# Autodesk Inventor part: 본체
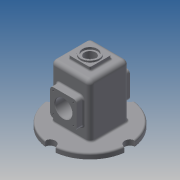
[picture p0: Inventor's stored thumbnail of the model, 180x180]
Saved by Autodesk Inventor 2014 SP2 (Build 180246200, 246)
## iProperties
Created: 2018-07
Part Number: 본체
Material: Generic
Document SubType Name: Modeling
Designer: cm
Density: 1 g/cm^3
Appearance: Default
Author: cm
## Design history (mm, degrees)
sketch "스케치1"
  geometry: L1 (-37, -37)-(37, -37); L2 (37, -37)-(37, 37); L3 (37, 37)-(-37, 37); L4 (-37, 37)-(-37, -37); L5 (-37, -37)-(37, 37); L6 (37, -37)-(-37, 37); 1 further point
  constraints: 12 end point, 2 midpoint, 2 parallel, 1 horizontal, 1 perpendicular
  dimensions: "d0" = 74 distance of L3.end L2.end; "d1" = 74 distance of L2.end L1.end
extrude "돌출1" new body sketch "스케치1" distance "d2" = 110; taper "d3" = 0 deg
feature "쉘1" dims "d5" = 5
sketch "스케치3"
  geometry: L1 (-37, -37)-(37, -37) reference; L2 (-37, 37)-(-37, -37) reference; L3 (37, 37)-(-37, 37) reference; L4 (37, -37)-(37, 37) reference; L5 (-29, -37)-(29, -37); L6 (37, -29)-(37, 29); L7 (29, 37)-(-29, 37); L8 (-37, 29)-(-37, -29); L9 (-37, -37)-(37, 37); L10 (37, -37)-(-37, 37); C1 r 75 at (0, 0); A1 r 8 centre (-29, -29) between (-37, -29) and (-29, -37) reference; A2 r 8 centre (-29, 29) between (-29, 37) and (-37, 29) reference; A3 r 8 centre (29, 29) between (37, 29) and (29, 37) reference; A4 r 8 centre (29, -29) between (29, -37) and (37, -29) reference; A5 r 8 centre (29, -29) between (29, -37) and (37, -29); A6 r 8 centre (-29, -29) between (-37, -29) and (-29, -37); A7 r 8 centre (-29, 29) between (-29, 37) and (-37, 29); A8 r 8 centre (29, 29) between (37, 29) and (29, 37); 1 further point
  constraints: 12 end point, 8 point on circle, 8 point on line, 8 tangent, 5 centre point, 3 equal radius, 2 midpoint, 2 parallel, 1 coincident, 1 horizontal, 1 perpendicular
  dimensions: "d9" = 150 diameter of C1; "d10" = 74 distance of L2.start L3.start; "d11" = 74 distance of L3.start L1.end; "d12" = 8 radius of A5
extrude "돌출3" join sketch "스케치3" distance "d13" = 10; taper "d14" = 0 deg
sketch "스케치4"
  geometry: L1 (0, 0)-(0, 55); L2 (-29, 105)-(29, 105) reference; L3 (-32, 0)-(-32, 102) reference; L4 (32, 102)-(32, 0) reference; L5 (0, 55)-(-49.301, 55); L6 (-32, 80)-(-25, 77.452); L7 (-25, 77.452)-(-25, 55); L8 (-32, 80)-(-32, 55); A1 r 3 centre (-29, 102) between (-29, 105) and (-32, 102) reference; A2 r 3 centre (29, 102) between (32, 102) and (29, 105) reference
  constraints: 10 end point, 4 point on line, 2 perpendicular, 1 vertical
  dimensions: "d15" = 55 distance of L1.start L1.end; "d16" = 7 distance between parallel lines of L7 L3; "d17" = 50 diameter of L6.start L5; "d18" = 110 deg angle of L6 L3
revolve "회전1" sketch "스케치4" stored, may be unused: angle "d19" = 90 deg
fillet "모깎기2" dims "d20" = 8
fillet "모깎기3" dims "d21" = 3
sketch "스케치6"
  geometry: L1 (0, 92)-(58, 92) reference; L2 (29, -10)-(29, 45); L3 (4, 70)-(54, 70); L4 (54, 70)-(54, 20); L5 (54, 20)-(4, 20); L6 (4, 20)-(4, 70); L7 (4, 70)-(54, 20); L8 (54, 70)-(4, 20)
  constraints: 14 end point, 2 midpoint, 2 parallel, 2 perpendicular, 1 horizontal
  dimensions: "d22" = 55 distance of L2.start L2.end; "d23" = 50 distance of L4.end L5.end; "d24" = 50 distance of L3.end L4.end
extrude "돌출4" join sketch "스케치6" distance "d25" = 13; taper "d26" = 0 deg
sketch "스케치7"
  geometry: L1 (54, 20)-(54, 70) reference; L2 (29, -10)-(29, 45); C1 r 16 at (29, 45)
  constraints: 2 end point, 1 centre point, 1 coincident, 1 parallel
  dimensions: "d27" = 55 distance of L2.start L2.end; "d28" = 32 diameter of C1
extrude "돌출5" cut sketch "스케치7" stored distance "d29" = 13; taper "d30" = 0 deg
sketch "스케치8"
  geometry: L1 (-20, 20)-(20, 20); L2 (20, 20)-(20, -20); L3 (20, -20)-(-20, -20); L4 (-20, -20)-(-20, 20); L5 (-20, 20)-(20, -20); L6 (20, 20)-(-20, -20); 1 further point
  constraints: 12 end point, 2 midpoint, 2 parallel, 1 horizontal, 1 perpendicular
  dimensions: "d31" = 40 distance of L2.end L3.end; "d32" = 40 distance of L1.end L2.end
extrude "돌출6" join sketch "스케치8" distance "d33" = 7; taper "d34" = 0 deg
sketch "스케치9"
  geometry: C1 r 17.5 at (0, 0); 1 further point
  constraints: 1 centre point, 1 coincident
  dimensions: "d35" = 35 diameter of C1
extrude "돌출7" join sketch "스케치9" distance "d36" = 3; taper "d37" = 0 deg
sketch "스케치10"
  geometry: C1 r 17.5 at (0, 0) reference; 1 further point
  constraints: 1 coincident
hole "구멍1" sketch "스케치10" at (0, 0) diameter "d38" = 21; stored, may be unused: countersink angle "d42" = 90 deg, drill point angle "d44" = 118 deg; dims "d39" = 6, "d40" = 28, "d41" = 4, "d43" = 8
fillet "모깎기4" dims "d45" = 6
fillet "모깎기5" dims "d46" = 3
fillet "모깎기6" dims "d47" = 6
fillet "모깎기7" dims "d48" = 3
sketch "스케치11"
  geometry: A1 r 6 centre (10, 26) between (4, 26) and (10, 20) reference; A2 r 6 centre (48, 26) between (48, 20) and (54, 26) reference; A3 r 6 centre (48, 64) between (54, 64) and (48, 70) reference; A4 r 6 centre (10, 64) between (10, 70) and (4, 64) reference; 5 further points
  constraints: 4 coincident
hole "구멍2" sketch "스케치11" at (10, 64), (48, 64), (48, 26), (10, 26) diameter "d49" = 3.242; stored, may be unused: countersink angle "d53" = 90 deg, drill point angle "d55" = 118 deg; dims "d50" = 8, "d51" = 28, "d52" = 4, "d54" = 10
fillet "모깎기8" dims "d56" = 3
fillet "모깎기9" dims "d57" = 3
fillet "모깎기10" dims "d58" = 3
fillet "모깎기11" dims "d59" = 3
sketch "스케치12"
  geometry: L1 (29, 40)-(-29, 40) reference; L2 (0, -75)-(0, 75); L3 (-75, 0)-(75, 0); C1 r 72 at (0, 0) reference; C2 r 10 at (0, 75); C3 r 10 at (75, 0); C4 r 10 at (0, -75); C5 r 10 at (-75, 0); A1 r 75 centre (0, 0) between (0, -75) and (0, 75) reference; 1 further point
  constraints: 5 coincident, 4 centre point, 4 end point, 4 point on circle, 2 midpoint, 2 perpendicular
  dimensions: "d61" = 20 diameter of C2; "d62" = 20 diameter of C3; "d63" = 20 diameter of C4; "d64" = 20 diameter of C5
extrude "돌출8" cut sketch "스케치12" stored distance "d65" = 3; taper "d66" = 0 deg
chamfer "모따기1" distance "d67" = 1; stored, may be unused: second distance "d68" = 2, angle "d69" = 45 deg
sketch "스케치14"
  geometry: L1 (11.5, -18)-(46.5, -18) reference; L2 (19.022, 102)-(38.978, 102) reference; 3 further points
  constraints: 1 midpoint, 1 vertical alignment, 1 other
  dimensions: "d70" = 30 distance from line of point (29, 12) L1
feature "엠보싱1" sketch "스케치14" dims "d0" = 74, "d1" = 74, "d10" = 74, "d71" = 0.5, "d72" = 0
node "솔리드1"
mirror "대칭1"
mirror "대칭2"
mirror "대칭3"
